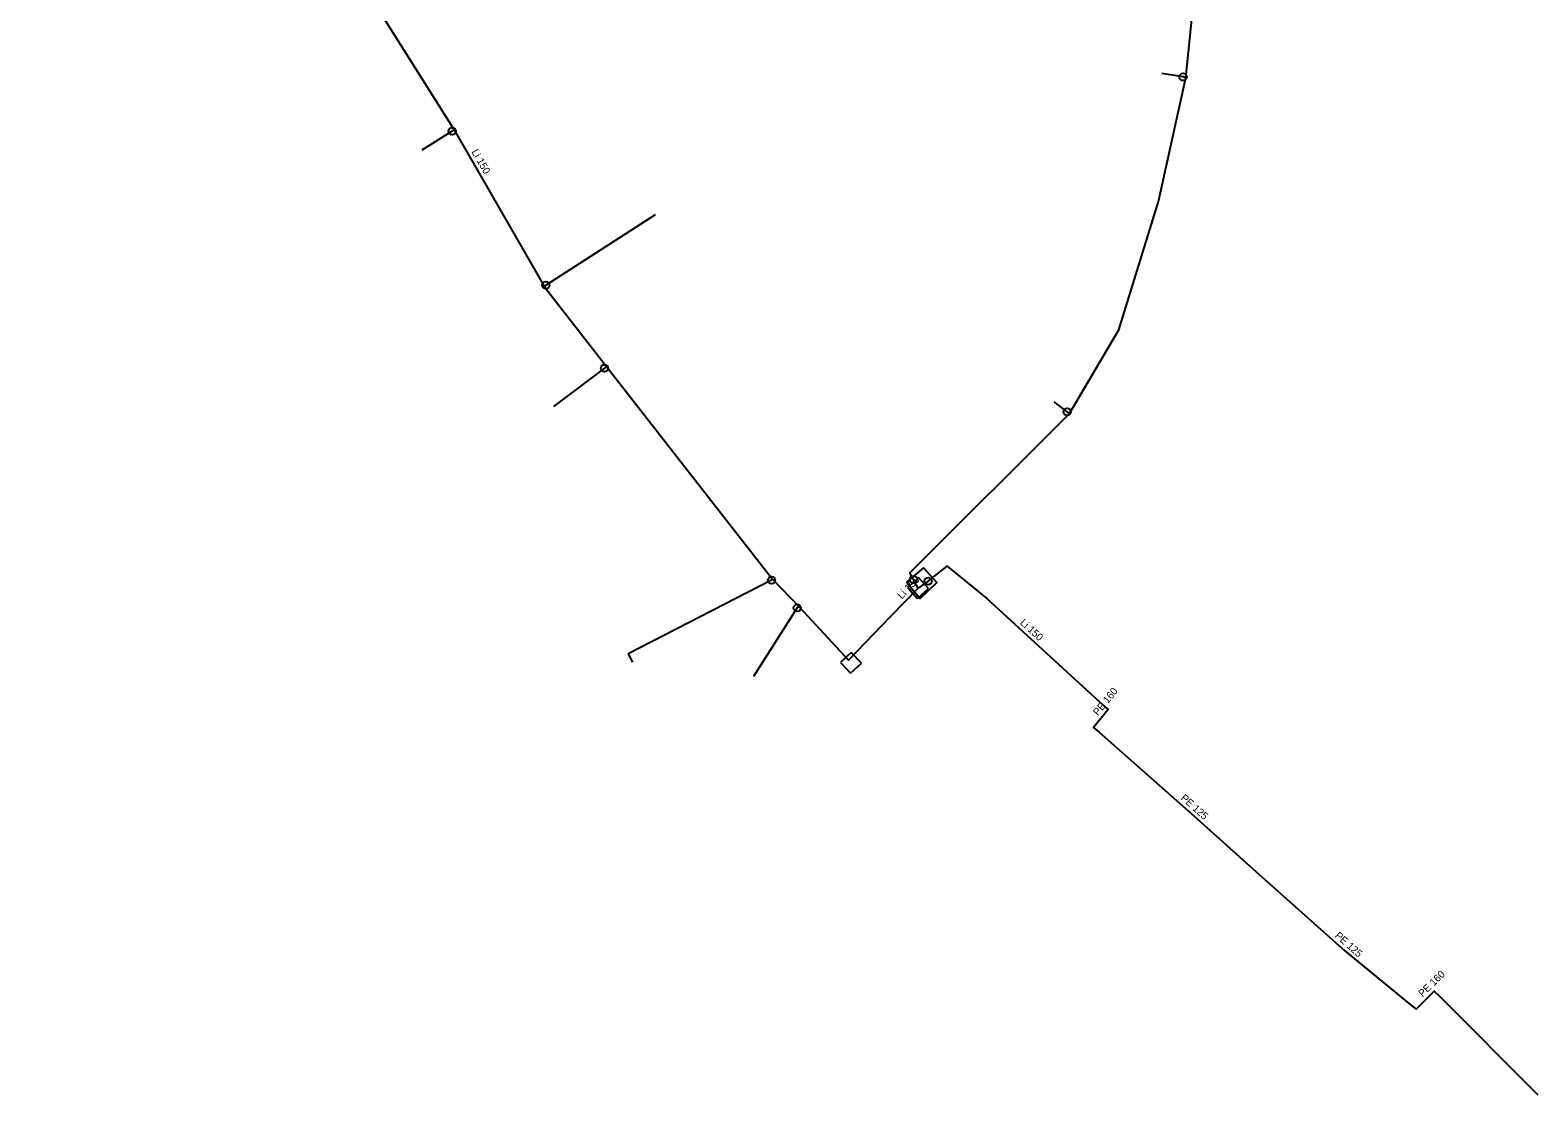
# Model space of a CAD drawing. Extents: x -684724 to -684366, y -1163865 to -1163489.
# Drawn here: x -684469.1 to -684366.3, y -1163864.8 to -1163792.2 of the extents above; entities that cross this region are included whole.
import ezdxf

# ---------------------------------------------------------------- set-up
doc = ezdxf.new("R2010")
doc.units = 0
for name, color, linetype in [('Objekty podzemní', 7, 'Continuous'), ('Popis vodovodních řadů', 7, 'Continuous'), ('Vod přípojky-voda pitná', 7, 'Continuous'), ('Vodovodní řad', 7, 'Continuous'), ('Vodovodní šachty', 7, 'Continuous'), ('Vodovodní šoupata', 7, 'Continuous')]:
    doc.layers.add(name, color=color, linetype=linetype)

msp = doc.modelspace()

# ---------------------------------------------------------------- linework, layer by layer
at = {"layer": 'Objekty podzemní'}
msp.add_lwpolyline([(-684409.37, -1163829.84), (-684408.42, -1163830.96), (-684407.28, -1163829.87), (-684408.21, -1163828.86), (-684409.37, -1163829.84)], dxfattribs=at)
at = {"layer": 'Vod přípojky-voda pitná'}
for points in [[(-684390.3, -1163795.45), (-684390.5, -1163795.38), (-684391.94, -1163795.15)], [(-684440.2, -1163798.98), (-684440.35, -1163799.07), (-684442.42, -1163800.37)], [(-684434.04, -1163809.69), (-684433.96, -1163809.59), (-684426.48, -1163804.77)], [(-684429.82, -1163815.12), (-684429.96, -1163815.24), (-684433.44, -1163817.87)], [(-684398.24, -1163818.34), (-684398.4, -1163818.23), (-684399.28, -1163817.53)], [(-684418.5, -1163829.64), (-684418.56, -1163829.71), (-684428.35, -1163834.72), (-684428.04, -1163835.29)], [(-684416.68, -1163831.53), (-684416.81, -1163831.6), (-684419.8, -1163836.28)]]:
    msp.add_lwpolyline(points, dxfattribs=at)
at = {"layer": 'Vodovodní řad'}
for points in [[(-684408.88, -1163829.66), (-684409.14, -1163829.21), (-684398.24, -1163818.34), (-684394.87, -1163812.64), (-684392.17, -1163803.88), (-684390.3, -1163795.45), (-684388.86, -1163781.22), (-684389.37, -1163767.49), (-684392.55, -1163747.46), (-684392.72, -1163746.65), (-684392.08, -1163746.64)], [(-684469.13, -1163763.98), (-684466.03, -1163766.59), (-684459.14, -1163773.18), (-684448.07, -1163786.84), (-684447.19, -1163787.9), (-684440.2, -1163798.98), (-684434.04, -1163809.69), (-684429.82, -1163815.12), (-684418.5, -1163829.64), (-684416.68, -1163831.53), (-684413.31, -1163835.17), (-684410.42, -1163832.17)], [(-684407.88, -1163829.77), (-684406.59, -1163828.74), (-684403.88, -1163830.96), (-684395.98, -1163838.21)], [(-684408.57, -1163830.24), (-684408.88, -1163829.66)], [(-684407.88, -1163829.77), (-684408.57, -1163830.24)], [(-684410.42, -1163832.17), (-684408.57, -1163830.24)], [(-684395.98, -1163838.21), (-684395.6, -1163838.53), (-684396.6, -1163839.76), (-684396.21, -1163840.08)], [(-684396.21, -1163840.08), (-684389.77, -1163845.79), (-684385.54, -1163849.57)], [(-684385.54, -1163849.57), (-684379.46, -1163854.98), (-684375, -1163858.64)], [(-684375, -1163858.64), (-684374.61, -1163858.96), (-684373.36, -1163857.74), (-684373.01, -1163858.09)], [(-684373.01, -1163858.09), (-684366.3, -1163864.81)]]:
    msp.add_lwpolyline(points, dxfattribs=at)
at = {"layer": 'Vodovodní šachty'}
for p, q in [((-684408.54, -1163829.53), (-684409.28, -1163830.21)), ((-684407.86, -1163830.27), (-684408.54, -1163829.53)), ((-684409.28, -1163830.21), (-684408.6, -1163830.95)), ((-684408.6, -1163830.95), (-684407.86, -1163830.27)), ((-684413.13, -1163834.63), (-684413.86, -1163835.32)), ((-684412.44, -1163835.36), (-684413.13, -1163834.63)), ((-684413.86, -1163835.32), (-684413.17, -1163836.05)), ((-684413.17, -1163836.05), (-684412.44, -1163835.36))]:
    msp.add_line(p, q, dxfattribs=at)
at = {"layer": 'Vodovodní šoupata'}
for centre in [(-684390.5, -1163795.38), (-684440.35, -1163799.07), (-684433.96, -1163809.59), (-684429.96, -1163815.24), (-684398.4, -1163818.23), (-684418.56, -1163829.71), (-684408.88, -1163829.66), (-684407.88, -1163829.77), (-684416.81, -1163831.6)]:
    msp.add_circle(centre, 0.25, dxfattribs=at)

# ---------------------------------------------------------------- texts
at = {"layer": 'Popis vodovodních řadů'}
for s, rotation, p in [('Li 150', 299.9059, (-684439.05, -1163800.48)), ('Li 150', 46.2124, (-684409.68, -1163831.03)), ('Li 150', 317.4567, (-684401.66, -1163832.66)), ('PE 160', 50.8886, (-684396.3, -1163838.99)), ('PE 125', 318.4383, (-684390.7, -1163844.63)), ('PE 125', 318.3372, (-684380.18, -1163854.01)), ('PE 160', 44.3041, (-684374.16, -1163858.17))]:
    msp.add_text(s, height=0.5, rotation=rotation, dxfattribs=at).set_placement(p)

doc.saveas('drawing.dxf')
